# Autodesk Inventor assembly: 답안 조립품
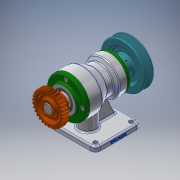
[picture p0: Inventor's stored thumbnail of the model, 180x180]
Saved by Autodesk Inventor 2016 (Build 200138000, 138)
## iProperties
Created: 2019-01
Part Number: 답안 조립품
Material: 일반
Document SubType Name: Assembly
Designer: USER
Author: USER
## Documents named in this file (15)
- C:\Users\USER\Desktop\490107V1031\답안 조립품.iam
- C:\Users\USER\Desktop\490107V1031\본체.ipt
- C:\Users\USER\Desktop\490107V1031\오일 실 25 38 8.ipt
- C:\Users\USER\Desktop\490107V1031\축.ipt
- C:\Users\USER\Desktop\490107V1031\키 5 x 5 x 20.ipt
- C:\Users\USER\Desktop\490107V1031\키 6 x 6 x 18.ipt
- C:\Users\USER\Desktop\490107V1031\V-벨트풀리.ipt
- C:\Users\USER\Desktop\490107V1031\뒤커버.ipt
- C:\Users\USER\Desktop\490107V1031\멈춤나사 M3.ipt
- C:\Users\USER\Desktop\490107V1031\베어링 6203.ipt
- C:\Users\USER\Desktop\490107V1031\베어링 6205.ipt
- C:\Users\USER\Desktop\490107V1031\볼트 M4.ipt
- C:\Users\USER\Desktop\490107V1031\스퍼기어.ipt
- C:\Users\USER\Desktop\490107V1031\앞커버.ipt
- C:\Users\USER\Desktop\490107V1031\오일 실 17 30 8.ipt
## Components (1 placed, 1 different names)
1. V-벨트풀리:1
